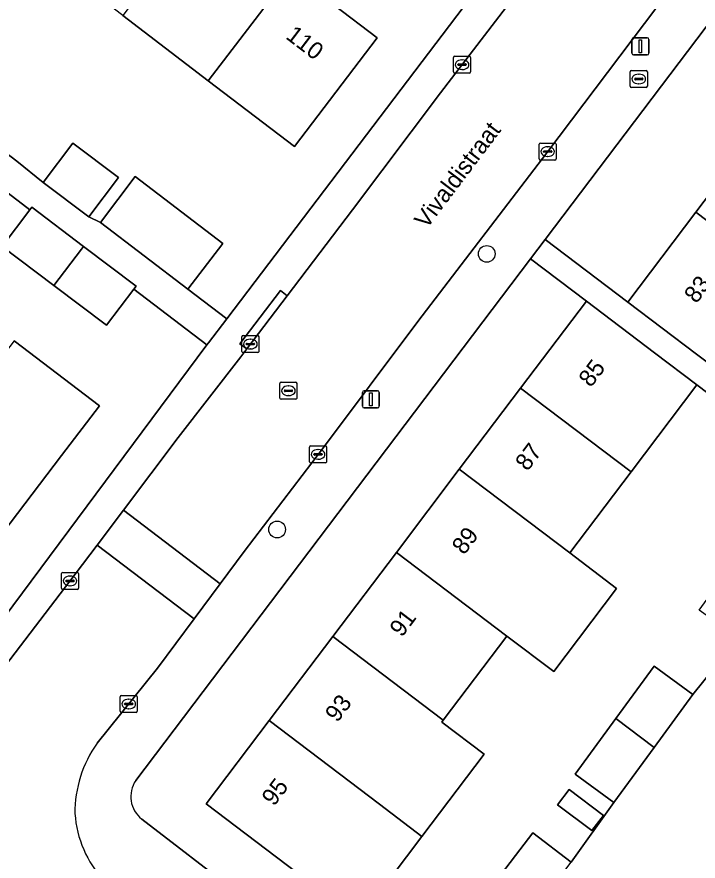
# Model space of a CAD drawing. Extents: x 159039 to 160102, y 381214 to 382524.
# Drawn here: x 159351.81 to 159391.67, y 381905.89 to 381955.27 of the extents above; entities that cross this region are included whole.
import ezdxf

# ---------------------------------------------------------------- set-up
doc = ezdxf.new("R2010")
doc.units = 0
for name, color, linetype in [('IMGEO_Boom', 7, 'Continuous'), ('IMGEO_Brandkraan', 7, 'Continuous'), ('IMGEO_Erf', 7, 'Continuous'), ('IMGEO_Kolk', 7, 'Continuous'), ('IMGEO_Lichtmast', 7, 'Continuous'), ('IMGEO_Openbare_ruimte_label', 7, 'Continuous'), ('IMGEO_Pand', 7, 'Continuous'), ('IMGEO_Pand_nummerreeks', 7, 'Continuous'), ('IMGEO_Rijbaan_lokaal_open', 7, 'Continuous'), ('IMGEO_Rioolput', 7, 'Continuous'), ('IMGEO_Voetpad_open', 7, 'Continuous')]:
    doc.layers.add(name, color=color, linetype=linetype)

msp = doc.modelspace()

# ---------------------------------------------------------------- linework, layer by layer
at = {"layer": 'IMGEO_Boom'}
for centre in [(159379.303, 381941.411), (159367.038, 381925.289)]:
    msp.add_circle(centre, 0.489, dxfattribs=at)
at = {"layer": 'IMGEO_Brandkraan'}
for p, q in [((159387.701, 381951.213), (159387.701, 381952.065)), ((159387.776, 381952.139), (159388.628, 381952.139)), ((159388.189, 381951.919), (159388.214, 381951.919)), ((159388.702, 381952.065), (159388.702, 381951.213)), ((159387.96, 381951.633), (159387.96, 381951.645)), ((159388.398, 381951.596), (159388, 381951.596)), ((159388.003, 381951.682), (159388.401, 381951.682)), ((159388.212, 381951.359), (159388.187, 381951.359)), ((159388.444, 381951.645), (159388.444, 381951.633)), ((159388.628, 381951.139), (159387.776, 381951.139))]:
    msp.add_line(p, q, dxfattribs=at)
for points in [[(159387.701, 381951.213), (159387.701, 381952.065)], [(159387.776, 381952.139), (159388.628, 381952.139)], [(159388.702, 381952.065), (159388.702, 381951.213)], [(159388.628, 381951.139), (159387.776, 381951.139)]]:
    msp.add_lwpolyline(points, dxfattribs=at)
for centre, radius, start, end in [((159387.778, 381952.063), 0.0765, 91.552, 178.448), ((159387.778, 381952.063), 0.0765, 91.552, 178.448), ((159388.626, 381952.063), 0.0765, 1.552, 88.448), ((159388.626, 381952.063), 0.0765, 1.552, 88.448), ((159388, 381951.642), 0.0403, 85.8775, 175.7526), ((159387.997, 381951.632), 0.0366, 178.938, 274.7102), ((159388.401, 381951.639), 0.043, 264.8664, 352.4533), ((159388.405, 381951.644), 0.0386, 1.7309, 96.639), ((159387.778, 381951.215), 0.0765, 181.552, 268.448), ((159387.778, 381951.215), 0.0765, 181.552, 268.448), ((159388.626, 381951.215), 0.0765, 271.552, 358.448), ((159388.626, 381951.215), 0.0765, 271.552, 358.448)]:
    msp.add_arc(centre, radius, start, end, dxfattribs=at)
for centre, major_axis, ratio, start_param, end_param in [((159388.188, 381951.639), (-0.387, 0.002), 0.722429, 4.712389, 7.853982), ((159388.213, 381951.639), (-0.39, 0.002), 0.717154, 1.570796, 4.712389)]:
    msp.add_ellipse(centre, major_axis=major_axis, ratio=ratio, start_param=start_param, end_param=end_param, dxfattribs=at)
at = {"layer": 'IMGEO_Erf'}
for points in [[(159349.879, 381948.295), (159351.809, 381946.835), (159353.352, 381945.577), (159355.089, 381947.888), (159357.757, 381945.882), (159356.02, 381943.572), (159356.692, 381943.254), (159358.738, 381945.935), (159363.866, 381942.023), (159361.82, 381939.341), (159364.085, 381937.613), (159378.352, 381956.413), (159350.613, 381977.649)], [(159347.838, 381973.159), (159353.074, 381969.165), (159357.993, 381965.412), (159362.847, 381961.708), (159367.855, 381957.888), (159372.898, 381954.04), (159368.05, 381947.686), (159363.007, 381951.533), (159357.999, 381955.354), (159353.145, 381959.057), (159348.226, 381962.81)], [(159349.407, 381917.941), (159362.932, 381936.091), (159358.66, 381939.35), (159357.045, 381937.233), (159353.963, 381939.563), (159350.945, 381941.845), (159352.571, 381943.995), (159352.395, 381944.129), (159348.939, 381946.765)], [(159369.35, 381904.35), (159362.881, 381909.247), (159366.564, 381914.112), (159370.29, 381919.034), (159374.014, 381923.953), (159377.694, 381928.814), (159381.285, 381933.558), (159385.134, 381938.642), (159381.864, 381941.117), (159358.765, 381910.606)], [(159351.641, 381936.334), (159356.635, 381932.524), (159354.423, 381929.625), (159349.244, 381922.836)], [(159389.093, 381917.303), (159391.36, 381915.647), (159394.01, 381918.924), (159391.743, 381920.58), (159394.123, 381923.839), (159396.364, 381926.908), (159398.631, 381925.252), (159400.124, 381927.297), (159391.603, 381933.745), (159387.754, 381928.661), (159384.163, 381923.917), (159386.906, 381921.84), (159383.226, 381916.979), (159380.483, 381919.056), (159376.759, 381914.137), (159376.674, 381914.024), (159379.154, 381912.146), (159375.514, 381907.337), (159371.965, 381902.649)], [(159359.115, 381908.355), (159376.15, 381895.237), (159376.238, 381895.351), (159378.01, 381897.652), (159378.049, 381897.703), (159375.313, 381899.789), (159379.036, 381904.671), (159379.173, 381904.851), (159379.655, 381904.484), (159381.994, 381907.552), (159384.249, 381905.832), (159386.739, 381909.319), (159384.472, 381910.975), (159386.852, 381914.234), (159389.093, 381917.303)]]:
    msp.add_lwpolyline(points, dxfattribs=at)
for points in [[(159398.917, 381953.594), (159402.704, 381958.596), (159397.868, 381962.257), (159382.726, 381942.256), (159387.562, 381938.595), (159391.54, 381943.85), (159395.265, 381948.769)], [(159386.131, 381908.565), (159385.456, 381907.674), (159383.45, 381909.193), (159384.124, 381910.084)]]:
    msp.add_lwpolyline(points, close=True, dxfattribs=at)
msp.add_arc((159360.137, 381909.667), 1.663, 145.6022, 232.0737, dxfattribs=at)
at = {"layer": 'IMGEO_Kolk'}
for p, q in [((159377.361, 381952.05), (159377.361, 381952.902)), ((159377.436, 381952.976), (159378.288, 381952.976)), ((159377.849, 381952.756), (159377.874, 381952.756)), ((159378.362, 381952.902), (159378.362, 381952.05)), ((159377.62, 381952.47), (159377.62, 381952.482)), ((159378.058, 381952.433), (159377.66, 381952.433)), ((159377.663, 381952.519), (159378.061, 381952.519)), ((159378.104, 381952.482), (159378.104, 381952.47)), ((159378.288, 381951.976), (159377.436, 381951.976)), ((159377.872, 381952.196), (159377.847, 381952.196)), ((159382.368, 381946.968), (159382.368, 381947.82)), ((159382.443, 381947.894), (159383.295, 381947.894)), ((159383.369, 381947.82), (159383.369, 381946.968)), ((159382.627, 381947.388), (159382.627, 381947.4)), ((159383.065, 381947.351), (159382.667, 381947.351)), ((159382.67, 381947.437), (159383.068, 381947.437)), ((159382.856, 381947.674), (159382.881, 381947.674)), ((159383.111, 381947.4), (159383.111, 381947.388)), ((159383.295, 381946.894), (159382.443, 381946.894)), ((159382.879, 381947.114), (159382.854, 381947.114)), ((159364.975, 381935.709), (159364.975, 381936.561)), ((159365.05, 381936.635), (159365.902, 381936.635)), ((159365.976, 381936.561), (159365.976, 381935.709)), ((159365.234, 381936.129), (159365.234, 381936.141)), ((159365.672, 381936.092), (159365.274, 381936.092)), ((159365.277, 381936.178), (159365.675, 381936.178)), ((159365.463, 381936.415), (159365.488, 381936.415)), ((159365.718, 381936.141), (159365.718, 381936.129)), ((159365.902, 381935.635), (159365.05, 381935.635)), ((159365.486, 381935.855), (159365.461, 381935.855)), ((159368.935, 381929.257), (159368.935, 381930.109)), ((159369.01, 381930.183), (159369.862, 381930.183)), ((159369.936, 381930.109), (159369.936, 381929.257)), ((159369.194, 381929.677), (159369.194, 381929.689)), ((159369.632, 381929.64), (159369.234, 381929.64)), ((159369.237, 381929.726), (159369.635, 381929.726)), ((159369.423, 381929.963), (159369.448, 381929.963)), ((159369.678, 381929.689), (159369.678, 381929.677)), ((159369.862, 381929.183), (159369.01, 381929.183)), ((159369.446, 381929.403), (159369.421, 381929.403)), ((159354.417, 381921.855), (159354.417, 381922.707)), ((159354.492, 381922.781), (159355.344, 381922.781)), ((159355.418, 381922.707), (159355.418, 381921.855)), ((159354.676, 381922.275), (159354.676, 381922.287)), ((159355.114, 381922.238), (159354.716, 381922.238)), ((159354.719, 381922.324), (159355.117, 381922.324)), ((159354.905, 381922.561), (159354.93, 381922.561)), ((159355.16, 381922.287), (159355.16, 381922.275)), ((159355.344, 381921.781), (159354.492, 381921.781)), ((159354.928, 381922.001), (159354.903, 381922.001)), ((159357.855, 381914.656), (159357.855, 381915.508)), ((159357.93, 381915.582), (159358.782, 381915.582)), ((159358.343, 381915.362), (159358.368, 381915.362)), ((159358.856, 381915.508), (159358.856, 381914.656)), ((159358.114, 381915.076), (159358.114, 381915.088)), ((159358.552, 381915.039), (159358.154, 381915.039)), ((159358.157, 381915.125), (159358.555, 381915.125)), ((159358.366, 381914.802), (159358.341, 381914.802)), ((159358.598, 381915.088), (159358.598, 381915.076)), ((159358.782, 381914.582), (159357.93, 381914.582))]:
    msp.add_line(p, q, dxfattribs=at)
for points in [[(159377.361, 381952.05), (159377.361, 381952.902)], [(159377.436, 381952.976), (159378.288, 381952.976)], [(159378.362, 381952.902), (159378.362, 381952.05)], [(159378.288, 381951.976), (159377.436, 381951.976)], [(159382.368, 381946.968), (159382.368, 381947.82)], [(159382.443, 381947.894), (159383.295, 381947.894)], [(159383.369, 381947.82), (159383.369, 381946.968)], [(159383.295, 381946.894), (159382.443, 381946.894)], [(159364.975, 381935.709), (159364.975, 381936.561)], [(159365.05, 381936.635), (159365.902, 381936.635)], [(159365.976, 381936.561), (159365.976, 381935.709)], [(159365.902, 381935.635), (159365.05, 381935.635)], [(159368.935, 381929.257), (159368.935, 381930.109)], [(159369.01, 381930.183), (159369.862, 381930.183)], [(159369.936, 381930.109), (159369.936, 381929.257)], [(159369.862, 381929.183), (159369.01, 381929.183)], [(159354.417, 381921.855), (159354.417, 381922.707)], [(159354.492, 381922.781), (159355.344, 381922.781)], [(159355.418, 381922.707), (159355.418, 381921.855)], [(159355.344, 381921.781), (159354.492, 381921.781)], [(159357.855, 381914.656), (159357.855, 381915.508)], [(159357.93, 381915.582), (159358.782, 381915.582)], [(159358.856, 381915.508), (159358.856, 381914.656)], [(159358.782, 381914.582), (159357.93, 381914.582)]]:
    msp.add_lwpolyline(points, dxfattribs=at)
for centre, radius, start, end in [((159377.438, 381952.9), 0.0765, 91.552, 178.448), ((159377.438, 381952.9), 0.0765, 91.552, 178.448), ((159378.286, 381952.9), 0.0765, 1.552, 88.448), ((159378.286, 381952.9), 0.0765, 1.552, 88.448), ((159377.66, 381952.479), 0.0403, 85.8775, 175.7526), ((159377.657, 381952.469), 0.0366, 178.938, 274.7102), ((159378.061, 381952.476), 0.043, 264.8664, 352.4533), ((159378.065, 381952.481), 0.0386, 1.7309, 96.639), ((159377.438, 381952.052), 0.0765, 181.552, 268.448), ((159377.438, 381952.052), 0.0765, 181.552, 268.448), ((159378.286, 381952.052), 0.0765, 271.552, 358.448), ((159378.286, 381952.052), 0.0765, 271.552, 358.448), ((159382.445, 381947.818), 0.0765, 91.552, 178.448), ((159382.445, 381947.818), 0.0765, 91.552, 178.448), ((159383.293, 381947.818), 0.0765, 1.552, 88.448), ((159383.293, 381947.818), 0.0765, 1.552, 88.448), ((159382.667, 381947.397), 0.0403, 85.8775, 175.7526), ((159382.664, 381947.387), 0.0366, 178.938, 274.7102), ((159383.068, 381947.394), 0.043, 264.8664, 352.4533), ((159383.072, 381947.399), 0.0386, 1.7309, 96.639), ((159382.445, 381946.97), 0.0765, 181.552, 268.448), ((159382.445, 381946.97), 0.0765, 181.552, 268.448), ((159383.293, 381946.97), 0.0765, 271.552, 358.448), ((159383.293, 381946.97), 0.0765, 271.552, 358.448), ((159365.052, 381936.559), 0.0765, 91.552, 178.448), ((159365.052, 381936.559), 0.0765, 91.552, 178.448), ((159365.9, 381936.559), 0.0765, 1.552, 88.448), ((159365.9, 381936.559), 0.0765, 1.552, 88.448), ((159365.274, 381936.138), 0.0403, 85.8775, 175.7526), ((159365.271, 381936.128), 0.0366, 178.938, 274.7102), ((159365.675, 381936.135), 0.043, 264.8664, 352.4533), ((159365.679, 381936.14), 0.0386, 1.7309, 96.639), ((159365.052, 381935.711), 0.0765, 181.552, 268.448), ((159365.052, 381935.711), 0.0765, 181.552, 268.448), ((159365.9, 381935.711), 0.0765, 271.552, 358.448), ((159365.9, 381935.711), 0.0765, 271.552, 358.448), ((159369.012, 381930.107), 0.0765, 91.552, 178.448), ((159369.012, 381930.107), 0.0765, 91.552, 178.448), ((159369.86, 381930.107), 0.0765, 1.552, 88.448), ((159369.86, 381930.107), 0.0765, 1.552, 88.448), ((159369.234, 381929.686), 0.0403, 85.8775, 175.7526), ((159369.231, 381929.676), 0.0366, 178.938, 274.7102), ((159369.635, 381929.683), 0.043, 264.8664, 352.4533), ((159369.639, 381929.688), 0.0386, 1.7309, 96.639), ((159369.012, 381929.259), 0.0765, 181.552, 268.448), ((159369.012, 381929.259), 0.0765, 181.552, 268.448), ((159369.86, 381929.259), 0.0765, 271.552, 358.448), ((159369.86, 381929.259), 0.0765, 271.552, 358.448), ((159354.494, 381922.705), 0.0765, 91.552, 178.448), ((159354.494, 381922.705), 0.0765, 91.552, 178.448), ((159355.342, 381922.705), 0.0765, 1.552, 88.448), ((159355.342, 381922.705), 0.0765, 1.552, 88.448), ((159354.716, 381922.284), 0.0403, 85.8775, 175.7526), ((159354.713, 381922.274), 0.0366, 178.938, 274.7102), ((159355.117, 381922.281), 0.043, 264.8664, 352.4533), ((159355.121, 381922.286), 0.0386, 1.7309, 96.639), ((159354.494, 381921.857), 0.0765, 181.552, 268.448), ((159354.494, 381921.857), 0.0765, 181.552, 268.448), ((159355.342, 381921.857), 0.0765, 271.552, 358.448), ((159355.342, 381921.857), 0.0765, 271.552, 358.448), ((159357.932, 381915.506), 0.0765, 91.552, 178.448), ((159357.932, 381915.506), 0.0765, 91.552, 178.448), ((159358.78, 381915.506), 0.0765, 1.552, 88.448), ((159358.78, 381915.506), 0.0765, 1.552, 88.448), ((159358.154, 381915.085), 0.0403, 85.8775, 175.7526), ((159358.151, 381915.075), 0.0366, 178.938, 274.7102), ((159358.555, 381915.082), 0.043, 264.8664, 352.4533), ((159358.559, 381915.087), 0.0386, 1.7309, 96.639), ((159357.932, 381914.658), 0.0765, 181.552, 268.448), ((159357.932, 381914.658), 0.0765, 181.552, 268.448), ((159358.78, 381914.658), 0.0765, 271.552, 358.448), ((159358.78, 381914.658), 0.0765, 271.552, 358.448)]:
    msp.add_arc(centre, radius, start, end, dxfattribs=at)
for centre, major_axis, ratio, start_param, end_param in [((159377.848, 381952.476), (-0.387, 0.002), 0.722429, 4.712389, 7.853982), ((159377.873, 381952.476), (-0.39, 0.002), 0.717154, 1.570796, 4.712389), ((159382.855, 381947.394), (-0.387, 0.002), 0.722429, 4.712389, 7.853982), ((159382.88, 381947.394), (-0.39, 0.002), 0.717154, 1.570796, 4.712389), ((159365.462, 381936.135), (-0.387, 0.002), 0.722429, 4.712389, 7.853982), ((159365.487, 381936.135), (-0.39, 0.002), 0.717154, 1.570796, 4.712389), ((159369.422, 381929.683), (-0.387, 0.002), 0.722429, 4.712389, 7.853982), ((159369.447, 381929.683), (-0.39, 0.002), 0.717154, 1.570796, 4.712389), ((159354.904, 381922.281), (-0.387, 0.002), 0.722429, 4.712389, 7.853982), ((159354.929, 381922.281), (-0.39, 0.002), 0.717154, 1.570796, 4.712389), ((159358.342, 381915.082), (-0.387, 0.002), 0.722429, 4.712389, 7.853982), ((159358.367, 381915.082), (-0.39, 0.002), 0.717154, 1.570796, 4.712389)]:
    msp.add_ellipse(centre, major_axis=major_axis, ratio=ratio, start_param=start_param, end_param=end_param, dxfattribs=at)
at = {"layer": 'IMGEO_Lichtmast'}
for p, q in [((159387.799, 381953.15), (159387.799, 381953.95)), ((159387.799, 381953.95), (159387.799, 381953.15)), ((159387.899, 381954.05), (159388.689, 381954.05)), ((159388.689, 381954.05), (159387.899, 381954.05)), ((159388.789, 381953.95), (159388.789, 381953.15)), ((159388.789, 381953.15), (159388.789, 381953.95)), ((159388.689, 381953.05), (159387.899, 381953.05)), ((159387.899, 381953.05), (159388.689, 381953.05)), ((159372.025, 381932.504), (159372.025, 381933.304)), ((159372.025, 381933.304), (159372.025, 381932.504)), ((159372.125, 381933.404), (159372.915, 381933.404)), ((159372.915, 381933.404), (159372.125, 381933.404)), ((159373.015, 381933.304), (159373.015, 381932.504)), ((159373.015, 381932.504), (159373.015, 381933.304)), ((159372.915, 381932.404), (159372.125, 381932.404)), ((159372.125, 381932.404), (159372.915, 381932.404))]:
    msp.add_line(p, q, dxfattribs=at)
for points in [[(159388.219, 381953.925), (159388.369, 381953.925), (159388.369, 381953.175), (159388.219, 381953.175), (159388.219, 381953.925)], [(159372.445, 381933.279), (159372.595, 381933.279), (159372.595, 381932.529), (159372.445, 381932.529), (159372.445, 381933.279)]]:
    msp.add_lwpolyline(points, dxfattribs=at)
for centre, start, end in [((159387.899, 381953.95), 90, 180), ((159387.899, 381953.95), 90, 180), ((159388.689, 381953.95), 0, 90), ((159388.689, 381953.95), 360, 90), ((159387.899, 381953.15), 180, 270), ((159387.899, 381953.15), 180, 270), ((159388.689, 381953.15), 270, 0), ((159388.689, 381953.15), 270, 0), ((159372.125, 381933.304), 90, 180), ((159372.125, 381933.304), 90, 180), ((159372.915, 381933.304), 0, 90), ((159372.915, 381933.304), 360, 90), ((159372.125, 381932.504), 180, 270), ((159372.125, 381932.504), 180, 270), ((159372.915, 381932.504), 270, 0), ((159372.915, 381932.504), 270, 0)]:
    msp.add_arc(centre, 0.1, start, end, dxfattribs=at)
at = {"layer": 'IMGEO_Pand'}
for points in [[(159357.999, 381955.354), (159363.007, 381951.533), (159367.855, 381957.888), (159362.847, 381961.708)], [(159367.855, 381957.888), (159363.007, 381951.533), (159368.05, 381947.686), (159372.898, 381954.04)], [(159400.585, 381944.741), (159395.265, 381948.769), (159391.54, 381943.85), (159396.861, 381939.821)], [(159355.089, 381947.888), (159353.352, 381945.577), (159356.02, 381943.572), (159357.757, 381945.882)], [(159361.82, 381939.341), (159363.866, 381942.023), (159358.738, 381945.935), (159356.692, 381943.254)], [(159355.707, 381941.849), (159352.679, 381944.138), (159352.571, 381943.995), (159350.945, 381941.845), (159353.963, 381939.563), (159355.588, 381941.693)], [(159396.861, 381939.821), (159391.54, 381943.85), (159387.562, 381938.595), (159391.585, 381935.549), (159392.883, 381934.567)], [(159358.66, 381939.35), (159358.789, 381939.519), (159355.707, 381941.849), (159355.588, 381941.693), (159353.963, 381939.563), (159357.045, 381937.233)], [(159387.754, 381928.661), (159391.603, 381933.745), (159389.12, 381935.624), (159385.134, 381938.642), (159381.285, 381933.558)], [(159354.423, 381929.625), (159356.635, 381932.524), (159351.641, 381936.334), (159349.429, 381933.435), (159349.34, 381933.503), (159344.161, 381926.714), (159349.244, 381922.836)], [(159384.163, 381923.917), (159387.754, 381928.661), (159381.285, 381933.558), (159377.694, 381928.814)], [(159377.694, 381928.814), (159374.014, 381923.953), (159380.483, 381919.056), (159383.226, 381916.979), (159386.906, 381921.84), (159384.163, 381923.917)], [(159376.759, 381914.137), (159380.483, 381919.056), (159374.014, 381923.953), (159370.29, 381919.034)], [(159370.29, 381919.034), (159366.564, 381914.112), (159373.033, 381909.215), (159375.514, 381907.337), (159379.154, 381912.146), (159376.674, 381914.024), (159376.759, 381914.137)], [(159386.852, 381914.234), (159389.091, 381912.54), (159391.36, 381915.647), (159389.093, 381917.303)], [(159386.852, 381914.234), (159384.472, 381910.975), (159386.739, 381909.319), (159389.091, 381912.54)], [(159366.564, 381914.112), (159362.881, 381909.247), (159369.35, 381904.35), (159369.484, 381904.527), (159371.965, 381902.649), (159375.514, 381907.337), (159373.033, 381909.215)], [(159385.456, 381907.674), (159386.131, 381908.565), (159384.124, 381910.084), (159383.45, 381909.193)], [(159379.036, 381904.671), (159381.779, 381902.594), (159384.249, 381905.832), (159381.994, 381907.552), (159379.655, 381904.484), (159379.173, 381904.851)]]:
    msp.add_lwpolyline(points, close=True, dxfattribs=at)
at = {"layer": 'IMGEO_Rijbaan_lokaal_open'}
for points in [[(159410.86, 381984.24), (159405.076, 381988.584), (159400.92, 381983.103), (159395.307, 381975.538), (159387.743, 381965.439), (159383.665, 381960.085), (159381.096, 381956.711), (159376.604, 381950.827), (159371.448, 381943.987), (159367.623, 381938.959), (159365.26, 381935.852), (159364.911, 381935.394), (159361.248, 381930.665), (159358.041, 381926.414), (159363.697, 381922.105), (159365.099, 381923.996), (159369.627, 381929.935), (159375.274, 381937.448), (159382.82, 381947.331), (159392.08, 381959.597), (159405.257, 381976.785)], [(159358.041, 381926.414), (159356.505, 381924.378), (159362.178, 381920.056), (159363.697, 381922.105)]]:
    msp.add_lwpolyline(points, close=True, dxfattribs=at)
for points in [[(159356.505, 381912.787), (159360.046, 381917.18), (159362.178, 381920.056), (159356.505, 381924.378), (159355.22, 381922.674), (159350.832, 381916.923)], [(159415.625, 381905.419), (159416.108, 381906.061), (159414.308, 381907.414), (159411.855, 381909.259), (159409.402, 381911.103), (159406.949, 381912.947), (159404.497, 381914.792), (159402.044, 381916.636), (159399.591, 381918.48), (159397.138, 381920.325), (159395.765, 381921.328), (159394.01, 381918.924), (159391.36, 381915.647), (159389.091, 381912.54), (159386.739, 381909.319), (159384.249, 381905.832)]]:
    msp.add_lwpolyline(points, dxfattribs=at)
for centre, radius, start, end in [((159362.182, 381908.731), 6.977, 144.4529, 180.4746), ((159361.624, 381909.122), 6.435, 184.0011, 222.738)]:
    msp.add_arc(centre, radius, start, end, dxfattribs=at)
at = {"layer": 'IMGEO_Rioolput'}
for p, q in [((159367.199, 381932.978), (159367.199, 381933.83)), ((159367.274, 381933.904), (159368.126, 381933.904)), ((159367.687, 381933.684), (159367.712, 381933.684)), ((159368.2, 381933.83), (159368.2, 381932.978)), ((159367.458, 381933.398), (159367.458, 381933.41)), ((159367.896, 381933.361), (159367.498, 381933.361)), ((159367.501, 381933.447), (159367.899, 381933.447)), ((159367.71, 381933.124), (159367.685, 381933.124)), ((159367.942, 381933.41), (159367.942, 381933.398)), ((159368.126, 381932.904), (159367.274, 381932.904))]:
    msp.add_line(p, q, dxfattribs=at)
for points in [[(159367.199, 381932.978), (159367.199, 381933.83)], [(159367.274, 381933.904), (159368.126, 381933.904)], [(159368.2, 381933.83), (159368.2, 381932.978)], [(159368.126, 381932.904), (159367.274, 381932.904)]]:
    msp.add_lwpolyline(points, dxfattribs=at)
for centre, radius, start, end in [((159367.276, 381933.828), 0.0765, 91.552, 178.448), ((159367.276, 381933.828), 0.0765, 91.552, 178.448), ((159368.124, 381933.828), 0.0765, 1.552, 88.448), ((159368.124, 381933.828), 0.0765, 1.552, 88.448), ((159367.498, 381933.407), 0.0403, 85.8775, 175.7526), ((159367.495, 381933.397), 0.0366, 178.938, 274.7102), ((159367.899, 381933.404), 0.043, 264.8664, 352.4533), ((159367.903, 381933.409), 0.0386, 1.7309, 96.639), ((159367.276, 381932.98), 0.0765, 181.552, 268.448), ((159367.276, 381932.98), 0.0765, 181.552, 268.448), ((159368.124, 381932.98), 0.0765, 271.552, 358.448), ((159368.124, 381932.98), 0.0765, 271.552, 358.448)]:
    msp.add_arc(centre, radius, start, end, dxfattribs=at)
for centre, major_axis, ratio, start_param, end_param in [((159367.686, 381933.404), (-0.387, 0.002), 0.722429, 4.712389, 7.853982), ((159367.711, 381933.404), (-0.39, 0.002), 0.717154, 1.570796, 4.712389)]:
    msp.add_ellipse(centre, major_axis=major_axis, ratio=ratio, start_param=start_param, end_param=end_param, dxfattribs=at)
at = {"layer": 'IMGEO_Voetpad_open'}
for points in [[(159364.911, 381935.394), (159365.26, 381935.852), (159364.864, 381936.156), (159367.227, 381939.263), (159367.623, 381938.959), (159371.448, 381943.987), (159376.604, 381950.827), (159381.096, 381956.711), (159383.665, 381960.085), (159387.743, 381965.439), (159395.307, 381975.538), (159400.92, 381983.103), (159405.076, 381988.584), (159406.641, 381990.648), (159408.558, 381993.176), (159413.105, 381999.127), (159413.438, 381999.563), (159413.774, 382000), (159416.185, 382003.138)], [(159411.384, 382000), (159398.618, 381983.116), (159397.577, 381981.74), (159383.263, 381962.809), (159381.764, 381960.886), (159379.871, 381958.305), (159379.509, 381957.83), (159378.352, 381956.413), (159364.085, 381937.613), (159363.026, 381936.217), (159362.932, 381936.091), (159349.407, 381917.941), (159348.619, 381918.534), (159345.009, 381914.041)], [(159421.514, 381998.432), (159415.967, 381991.036), (159412.416, 381986.311), (159410.86, 381984.24), (159405.257, 381976.785), (159392.08, 381959.597), (159382.82, 381947.331), (159375.274, 381937.448), (159369.627, 381929.935), (159365.099, 381923.996), (159363.697, 381922.105), (159362.178, 381920.056), (159360.046, 381917.18), (159356.505, 381912.787)], [(159358.765, 381910.606), (159381.864, 381941.117), (159382.726, 381942.256), (159397.868, 381962.257), (159398.906, 381963.628), (159421.683, 381993.713)], [(159348.939, 381946.765), (159352.395, 381944.129), (159352.571, 381943.995), (159352.679, 381944.138), (159355.707, 381941.849), (159358.789, 381939.519), (159358.66, 381939.35), (159362.932, 381936.091), (159363.026, 381936.217), (159364.085, 381937.613), (159361.82, 381939.341), (159356.692, 381943.254), (159356.02, 381943.572), (159353.352, 381945.577), (159351.809, 381946.835), (159349.879, 381948.295)], [(159392.883, 381934.567), (159391.585, 381935.549), (159387.562, 381938.595), (159382.726, 381942.256), (159381.864, 381941.117), (159385.134, 381938.642), (159389.12, 381935.624), (159391.603, 381933.745), (159400.124, 381927.297)], [(159343.639, 381907.464), (159349.936, 381915.749), (159350.832, 381916.923), (159355.22, 381922.674), (159356.505, 381924.378), (159358.041, 381926.414), (159361.248, 381930.665), (159364.911, 381935.394)], [(159426.351, 381856.153), (159422.295, 381858.998), (159406.652, 381869.933), (159405.497, 381870.741), (159380.139, 381888.468), (159383.125, 381892.481), (159382.87, 381892.674), (159383.434, 381893.418), (159382.253, 381894.34), (159378.501, 381889.532), (159375.388, 381891.962), (159379.14, 381896.769), (159378.01, 381897.652), (159376.238, 381895.351), (159376.15, 381895.237), (159359.115, 381908.355)]]:
    msp.add_lwpolyline(points, dxfattribs=at)
msp.add_lwpolyline([(159367.623, 381938.959), (159367.227, 381939.263), (159364.864, 381936.156), (159365.26, 381935.852)], close=True, dxfattribs=at)
for centre, radius, start, end in [((159362.182, 381908.731), 6.977, 144.4529, 180.4746), ((159360.137, 381909.667), 1.663, 145.6022, 232.0737), ((159361.624, 381909.122), 6.435, 184.0011, 222.738)]:
    msp.add_arc(centre, radius, start, end, dxfattribs=at)

# ---------------------------------------------------------------- texts
at = {"layer": 'IMGEO_Openbare_ruimte_label'}
msp.add_text('Vivaldistraat', height=1, rotation=52.9239, dxfattribs=at).set_placement((159375.784, 381942.828))
at = {"layer": 'IMGEO_Pand_nummerreeks'}
for s, rotation, p in [('110', 322.659, (159367.482, 381954.047)), ('83', 52.872, (159391.571, 381938.457)), ('85', 52.8731, (159385.396, 381933.554)), ('87', 52.8731, (159381.687, 381928.655)), ('89', 52.8725, (159377.978, 381923.756)), ('91', 52.8731, (159374.337, 381918.947)), ('93', 52.8725, (159370.56, 381913.957)), ('95', 52.8725, (159366.852, 381909.058))]:
    msp.add_text(s, height=1, rotation=rotation, dxfattribs=at).set_placement(p)

doc.saveas('drawing.dxf')
